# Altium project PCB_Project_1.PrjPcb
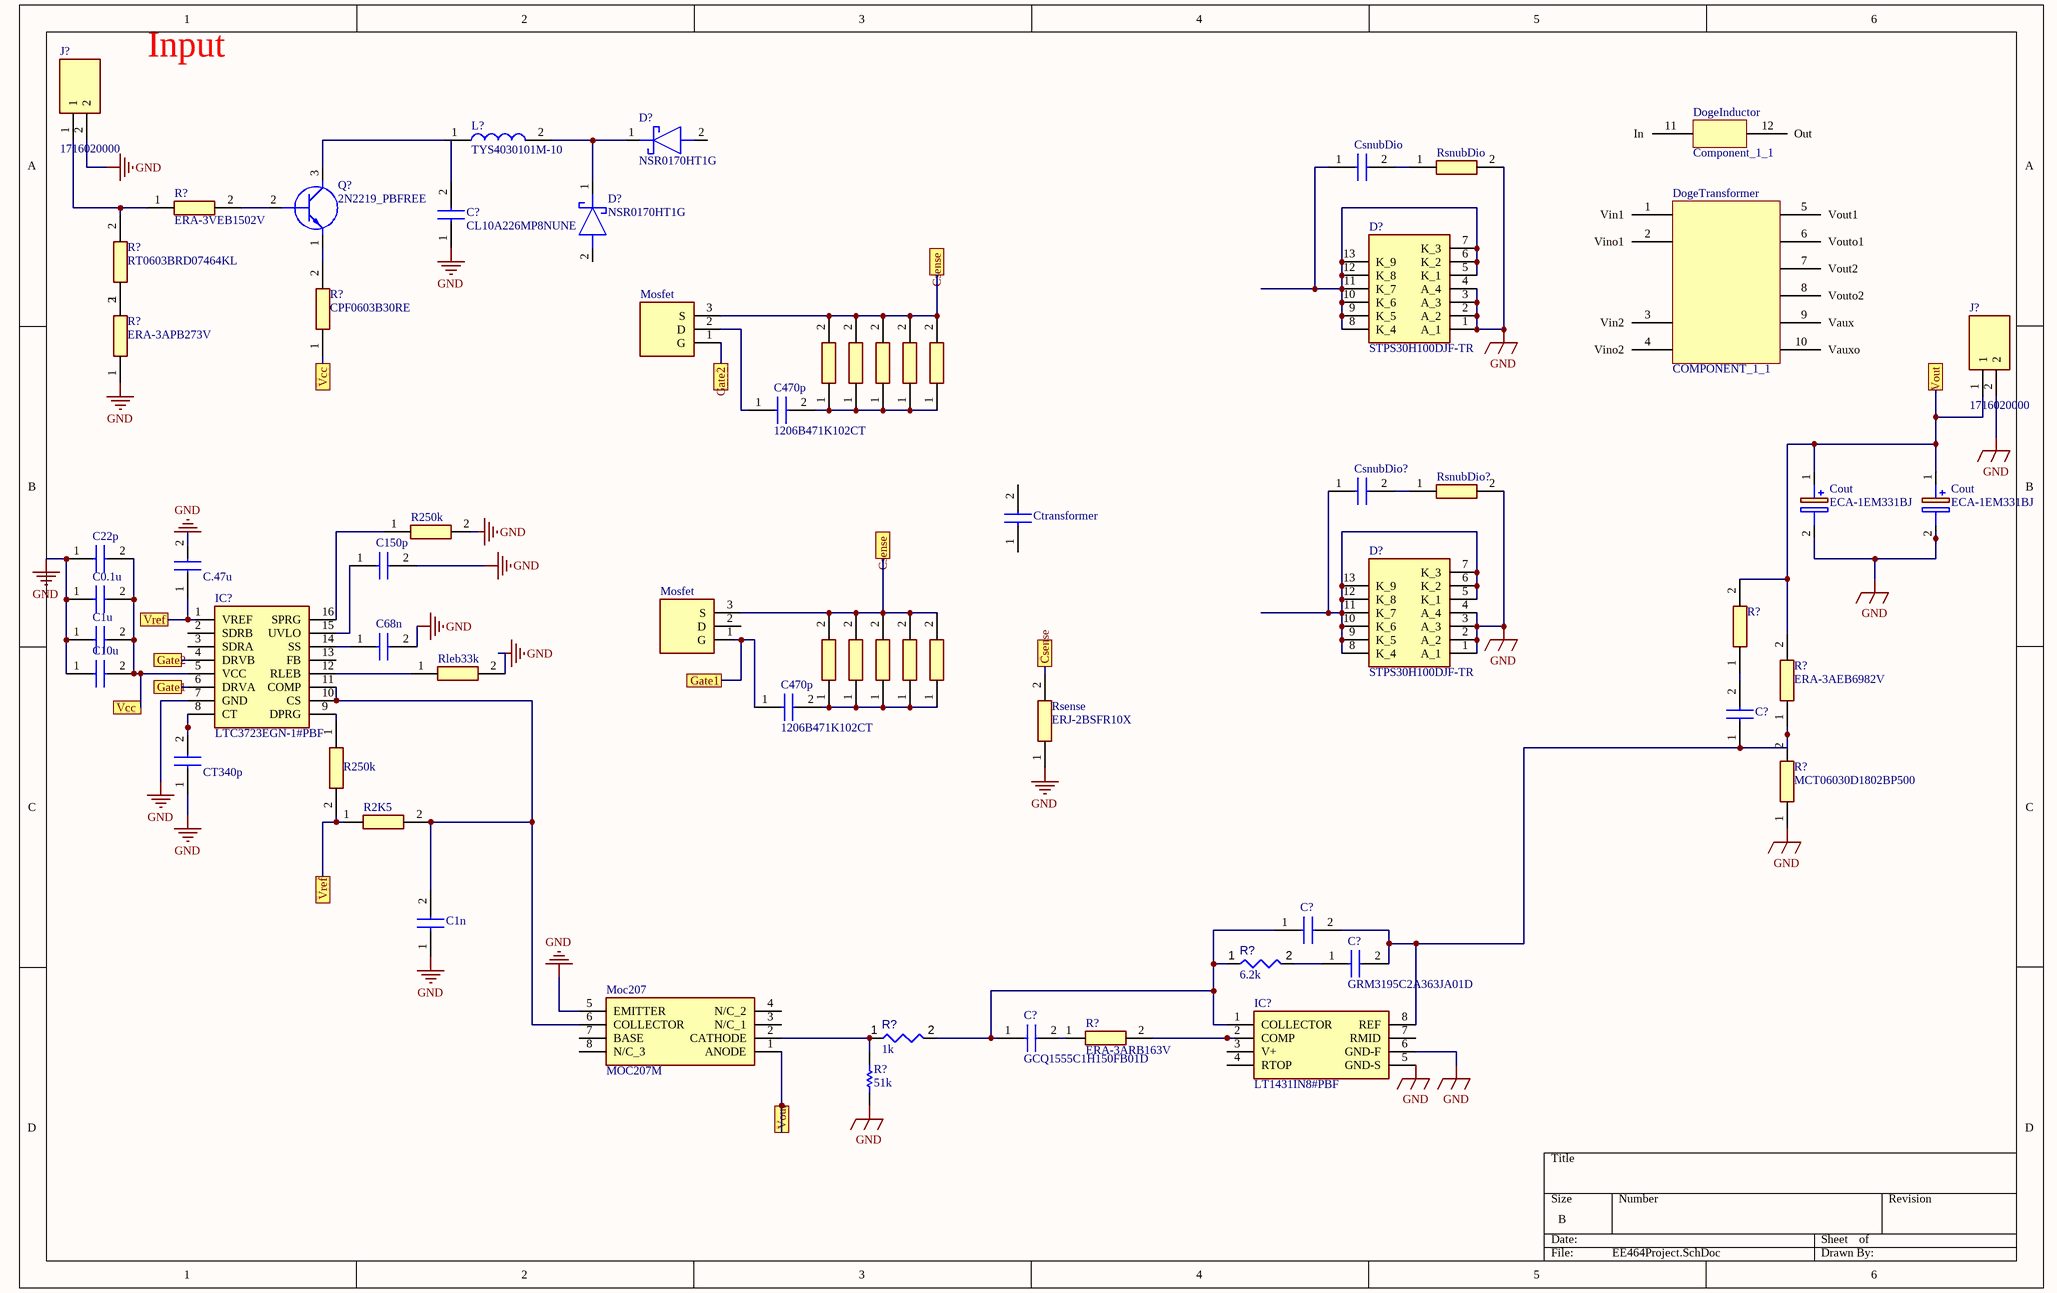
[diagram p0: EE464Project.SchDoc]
1 sheet, 64 parts. Net scope: flat (ports and power ports of the same name join across sheets).
Board file: EE464Project.PcbDoc

## Sheet EE464Project.SchDoc
size B; SheetNumber: 1; SheetTotal: 1

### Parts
(Parts that share a designator on the sheet are numbered #1, #2 ... from top to bottom, then left to right.)
C0.1u  06031C104K4Z2A  [CAPC1608X90N]  (value not drawn)
C1n  04025C102JAT2A  [CAPC1005X56N]  (value not drawn)
C1u  C1608X5R1H105K080AB  [CAPC1608X80N]  (value not drawn)
C10u  CL31A106MBHNNNE  [CAPC3216X180N]  (value not drawn)
C22p  06035A220JAT2A  [CAPC1608X90N]  (value not drawn)
C68n  885012206070  [CAPC1608X87N]  (value not drawn)
C150p  CL10C151JB8NNNC  [CAPC1608X90N]  (value not drawn)
C470p#1  1206B471K102CT  [CAPC3216X180N]
C470p#2  1206B471K102CT  [CAPC3216X180N]
C.47u  CGA4J1X8L1H474K125AE  [CAPC2012X145N]  (value not drawn)
C?#1  CL10A226MP8NUNE  [CAPC1608X105N]
C?#2  GRM21B5C2J222FWAAL  [CAPC2012X145N]  (value not drawn)
C?#3  C0402C121K8RACTU  [CAPC1005X55N]  (value not drawn)
C?#4  GRM3195C2A363JA01D  [CAPC3216X95N]
C?#5  GCQ1555C1H150FB01D  [CAPC1005X55N]
Cout#1  ECA-1EM331BJ  [CAPPRD350W65D825H1250]
Cout#2  ECA-1EM331BJ  [CAPPRD350W65D825H1250]
CsnubDio  GRM1885C2A201JA01D  [CAPC1608X90N]  (value not drawn)
CsnubDio?  GRM1885C2A201JA01D  [CAPC1608X90N]  (value not drawn)
CT340p  GRM1885C2A361JA01D  [CAPC1608X90N]  (value not drawn)
Ctransformer  C1210C104KBRACAUTO  [CAPC3225X280N]  (value not drawn)
D?#1  NSR0170HT1G  [SOD2512X100N]
D?#2  NSR0170HT1G  [SOD2512X100N]
D?#3  STPS30H100DJF-TR  [STPS30H100DJFTR]
D?#4  STPS30H100DJF-TR  [STPS30H100DJFTR]
DogeInductor  Component_1_1  [inductor]
DogeTransformer  COMPONENT_1_1  [transformer]
IC?#1  LTC3723EGN-1#PBF  [SOP64P601X175-16N]
IC?#2  LT1431IN8#PBF  [DIP794W53P254L1016H394Q8N]
J?#1  1716020000  [1716020000]
J?#2  1716020000  [1716020000]
L?  TYS4030101M-10  [INDPM4040X300N]
Moc207  MOC207M  [SOIC127P594X363-8N]
Mosfet#1  STW11NK100Z  [TO545P515X1560X2445-3P]  (value not drawn)
Mosfet#2  STW11NK100Z  [TO545P515X1560X2445-3P]  (value not drawn)
Q?  2N2219_PBFREE  [2N3440PBFREE]
R2K5  ERA-3AED2491V  [ERA3AEB101V]  (value not drawn)
R250k#1  MCT06030C2493FP500  [RESC1608X55N]  (value not drawn)
R250k#2  MCT06030C2493FP500  [RESC1608X55N]  (value not drawn)
R?#1  ERA-3VEB1502V  [RESC1608X55N]
R?#2  RT0603BRD07464KL  [RESC1608X55N]
R?#3  CPF0603B30RE  [RESC1608X55N]
R?#4  ERA-3APB273V  [ERA3AEB101V]
R?#5  CPF0603B3K32E  [RESC1608X55N]  (value not drawn)
R?#6  ERA-3AEB6982V  [ERA3AEB101V]
R?#7  MCT06030D1802BP500  [RESC1608X55N]
R?#8  value 6.2k  [RESC0402(1005)_L]  (hidden comment: Resistor 6K2  +/-5 % 0402 63 mW)
R?#9  value 1k  [RESC0805(2012)_L]  (hidden comment: 1KR5J)
R?#10  ERA-3ARB163V  [ERA3AEB101V]
R?#11  value 51k  [RESC1005X40X25ML05T10]  (hidden comment: Resistor 51k +/-5% 0402 63 mW)
Rleb33k  ERA-3AED333V  [ERA3AEB101V]  (value not drawn)
Rsense  ERJ-2BSFR10X  [RESC1005X40N]
RsnubDio  RC0603FR-1022RL  [RESC1608X55N]  (value not drawn)
RsnubDio?  RC0603FR-1022RL  [RESC1608X55N]  (value not drawn)
Rsnubmos  CRGH2512F221R  [RESC6432X65N]  (value not drawn)
Rsnubmos?#1  CRGH2512F221R  [RESC6432X65N]  (value not drawn)
Rsnubmos?#2  CRGH2512F221R  [RESC6432X65N]  (value not drawn)
Rsnubmos?#3  CRGH2512F221R  [RESC6432X65N]  (value not drawn)
Rsnubmos?#4  CRGH2512F221R  [RESC6432X65N]  (value not drawn)
Rsnubmos?#5  CRGH2512F221R  [RESC6432X65N]  (value not drawn)
Rsnubmos?#6  CRGH2512F221R  [RESC6432X65N]  (value not drawn)
Rsnubmos?#7  CRGH2512F221R  [RESC6432X65N]  (value not drawn)
Rsnubmos?#8  CRGH2512F221R  [RESC6432X65N]  (value not drawn)
Rsnubmos?#9  CRGH2512F221R  [RESC6432X65N]  (value not drawn)

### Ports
Csense, Gate1, Gate2, Vcc, Vout, Vref

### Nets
GND: C0.1u.1 C1n.1 C1u.1 C10u.1 C22p.1 C68n.2 C150p.2 C.47u.2 C?#1.1 Cout#1.2(-) Cout#2.2(-) CT340p.1 D?#3.1(A_1) D?#3.2(A_2) D?#3.3(A_3) D?#3.4(A_4) D?#4.1(A_1) D?#4.2(A_2) D?#4.3(A_3) D?#4.4(A_4) IC?#1.7(GND) IC?#2.5(GND-S) IC?#2.6(GND-F) J?#1.2 J?#2.2 Moc207.5(EMITTER) R250k#1.2 R?#4.1 R?#7.1 R?#11.1 Rleb33k.2 Rsense.1 RsnubDio.2 RsnubDio?.2
NetC0.1u_2: C0.1u.2 C1u.2 C10u.2 C22p.2 IC?#1.5(VCC) R?#3.1 ; port Vcc
NetC1n_2: C1n.2 IC?#1.10(CS) IC?#1.11(COMP) Moc207.6(COLLECTOR) R2K5.2
NetC68n_1: C68n.1 IC?#1.14(SS)
NetC150p_1: C150p.1 IC?#1.15(UVLO)
NetC470p#1_1: C470p#1.1 Mosfet#1.2(D)
NetC470p#1_2: C470p#1.2 Rsnubmos?#1.1 Rsnubmos?#2.1 Rsnubmos?#3.1 Rsnubmos?#4.1 Rsnubmos?#5.1
NetC470p#2_1: C470p#2.1 IC?#1.6(DRVA) Mosfet#2.1(G) ; port Gate1
NetC470p#2_2: C470p#2.2 Rsnubmos.1 Rsnubmos?#6.1 Rsnubmos?#7.1 Rsnubmos?#8.1 Rsnubmos?#9.1
NetC.47u_1: C.47u.1 IC?#1.1(VREF) R2K5.1 R250k#2.2 ; port Vref
NetC?#2_1: C?#2.1 C?#3.2 C?#4.2 IC?#2.8(REF) R?#6.1 R?#7.2
NetC?#2_2: C?#2.2 R?#5.1
NetC?#3_1: C?#3.1 C?#5.1 IC?#2.1(COLLECTOR) R?#8.1 R?#9.2
NetC?#4_1: C?#4.1 R?#8.2
NetC?#5_2: C?#5.2 R?#10.1
NetCout#1_1: Cout#1.1(+) Cout#2.1(+) J?#2.1 Moc207.1(ANODE) R?#5.2 R?#6.2 ; port Vout
NetCsnubDio?_1: CsnubDio?.1 D?#4.5(K_1) D?#4.6(K_2) D?#4.7(K_3) D?#4.8(K_4) D?#4.9(K_5) D?#4.10(K_6) D?#4.11(K_7) D?#4.12(K_8) D?#4.13(K_9)
NetCsnubDio?_2: CsnubDio?.2 RsnubDio?.1
NetCsnubDio_1: CsnubDio.1 D?#3.5(K_1) D?#3.6(K_2) D?#3.7(K_3) D?#3.8(K_4) D?#3.9(K_5) D?#3.10(K_6) D?#3.11(K_7) D?#3.12(K_8) D?#3.13(K_9)
NetCsnubDio_2: CsnubDio.2 RsnubDio.1
NetCT340p_2: CT340p.2 IC?#1.8(CT)
NetD?#1_1: D?#1.1(K) D?#2.1(K) L?.2
NetIC?#1_4: IC?#1.4(DRVB) Mosfet#1.1(G) ; port Gate2
NetIC?#1_9: IC?#1.9(DPRG) R250k#2.1
NetIC?#1_12: IC?#1.12(RLEB) Rleb33k.1
NetIC?#1_16: IC?#1.16(SPRG) R250k#1.1
NetIC?#2_2: IC?#2.2(COMP) R?#10.2
NetJ?#1_1: J?#1.1 R?#1.1 R?#2.2
NetL?_1: L?.1 Q?.3(C)
NetMoc207_2: Moc207.2(CATHODE) R?#9.1 R?#11.2
NetMosfet#1_3: Mosfet#1.3(S) Mosfet#2.3(S) Rsense.2 Rsnubmos.2 Rsnubmos?#1.2 Rsnubmos?#2.2 Rsnubmos?#3.2 Rsnubmos?#4.2 Rsnubmos?#5.2 Rsnubmos?#6.2 Rsnubmos?#7.2 Rsnubmos?#8.2 Rsnubmos?#9.2 ; port Csense
NetQ?_1: Q?.1(E) R?#3.2
NetQ?_2: Q?.2(B) R?#1.2

Not connected (* = marked no-connect by the designer): C?#1 2; Ctransformer 1 2; D?#1 2(A); D?#2 2(A); DogeInductor 11(In) 12(Out); DogeTransformer 1(Vin1) 2(Vino1) 3(Vin2) 4(Vino2) 5(Vout1) 6(Vouto1) 7(Vout2) 8(Vouto2) 9(Vaux) 10(Vauxo); IC?#1 2(SDRB) 3(SDRA) 13(FB); IC?#2 3(V+) 4(RTOP) 7(RMID); Moc207 3(N/C_1) 4(N/C_2) 7(BASE) 8(N/C_3); Mosfet#2 2(D); R?#2 1; R?#4 2

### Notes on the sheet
- Input

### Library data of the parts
C0.1u = 06031C104K4Z2A: Capacitor; Manufacturer_Name: AVX
C1n = 04025C102JAT2A: Capacitor; Manufacturer_Name: AVX
C1u = C1608X5R1H105K080AB: Capacitor; Manufacturer_Name: TDK
C10u = CL31A106MBHNNNE: Capacitor; Manufacturer_Name: Samsung Electro-Mechanics
C22p = 06035A220JAT2A: Capacitor; Manufacturer_Name: AVX
C68n = 885012206070: Capacitor; Manufacturer_Name: Wurth Elektronik
C150p = CL10C151JB8NNNC: Capacitor; Manufacturer_Name: Samsung Electro-Mechanics
C470p#1 C470p#2 = 1206B471K102CT: Capacitor; Manufacturer_Name: Walsin Technology Corporation
C.47u = CGA4J1X8L1H474K125AE: Capacitor; Manufacturer_Name: TDK
C?#1 = CL10A226MP8NUNE: Capacitor; Manufacturer_Name: Samsung Electro-Mechanics
C?#2 = GRM21B5C2J222FWAAL: Capacitor; Manufacturer_Name: Murata Electronics
C?#3 = C0402C121K8RACTU: Capacitor; Manufacturer_Name: Kemet
C?#4 = GRM3195C2A363JA01D: Capacitor; Manufacturer_Name: Murata Electronics
C?#5 = GCQ1555C1H150FB01D: Capacitor; Manufacturer_Name: Murata Electronics
Cout#1 Cout#2 = ECA-1EM331BJ: Capacitor Polarised; Manufacturer_Name: Panasonic
CsnubDio CsnubDio? = GRM1885C2A201JA01D: Capacitor; Manufacturer_Name: Murata Electronics
CT340p = GRM1885C2A361JA01D: Capacitor; Manufacturer_Name: Murata Electronics
Ctransformer = C1210C104KBRACAUTO: Capacitor; Manufacturer_Name: Kemet
D?#1 D?#2 = NSR0170HT1G: Schottky Diode; Manufacturer_Name: ON Semiconductor
D?#3 D?#4 = STPS30H100DJF-TR: Schottky Diode; Manufacturer_Name: STMicroelectronics
DogeInductor = Component_1_1: Doge
DogeTransformer = COMPONENT_1_1: Doge
IC?#1 = LTC3723EGN-1#PBF: Integrated Circuit; Manufacturer_Name: Linear Technology
IC?#2 = LT1431IN8#PBF: Integrated Circuit; Manufacturer_Name: Linear Technology
J?#1 J?#2 = 1716020000: Connector; Manufacturer_Name: Weidmuller
L? = TYS4030101M-10: Inductor; Manufacturer_Name: Laird Performance Materials
Moc207 = MOC207M: Integrated Circuit; Manufacturer_Name: ON Semiconductor
Mosfet#1 Mosfet#2 = STW11NK100Z: Integrated Circuit; Manufacturer_Name: STMicroelectronics
Q? = 2N2219_PBFREE: Transistor BJT NPN; Manufacturer_Name: Central Semiconductor; Manufacturer_Part_Number: 2N2219 PBFREE
R2K5 = ERA-3AED2491V: Resistor; Manufacturer_Name: Panasonic
R250k#1 R250k#2 = MCT06030C2493FP500: Resistor; Manufacturer_Name: Vishay
R?#1 = ERA-3VEB1502V: Resistor; Manufacturer_Name: Panasonic
R?#2 = RT0603BRD07464KL: Resistor; Manufacturer_Name: YAGEO (PHYCOMP)
R?#3 = CPF0603B30RE: Resistor; Manufacturer_Name: TE Connectivity
R?#4 = ERA-3APB273V: Resistor; Manufacturer_Name: Panasonic
R?#5 = CPF0603B3K32E: Resistor; Manufacturer_Name: TE Connectivity
R?#6 = ERA-3AEB6982V: Resistor; Manufacturer_Name: Panasonic
R?#7 = MCT06030D1802BP500: Resistor; Manufacturer_Name: Vishay
R?#8 = CMP-009-00147-3: Chip Resistor, 6,2 kOhms, +/-5 %, 63 mW, -55 to 155 degC, 0402; Tolerance: 5%; Power: 63mW
R?#9 = CMP-009-00076-2: 1K 0.125W 5% 0805 (2012 Metric)  SMD; Power: 125mW
R?#10 = ERA-3ARB163V: Resistor; Manufacturer_Name: Panasonic
R?#11 = CMP-009-00000-5: Chip Resistor, 51 KOhm, +/- 5%, 0.063 W, -55 to 155 degC, 0402 (1005 Metric); Power: 63mW
Rleb33k = ERA-3AED333V: Resistor; Manufacturer_Name: Panasonic
Rsense = ERJ-2BSFR10X: Resistor; Manufacturer_Name: Panasonic
RsnubDio RsnubDio? = RC0603FR-1022RL: Resistor; Manufacturer_Name: YAGEO (PHYCOMP)
Rsnubmos Rsnubmos?#1-Rsnubmos?#9 = CRGH2512F221R: Resistor; Manufacturer_Name: TE Connectivity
